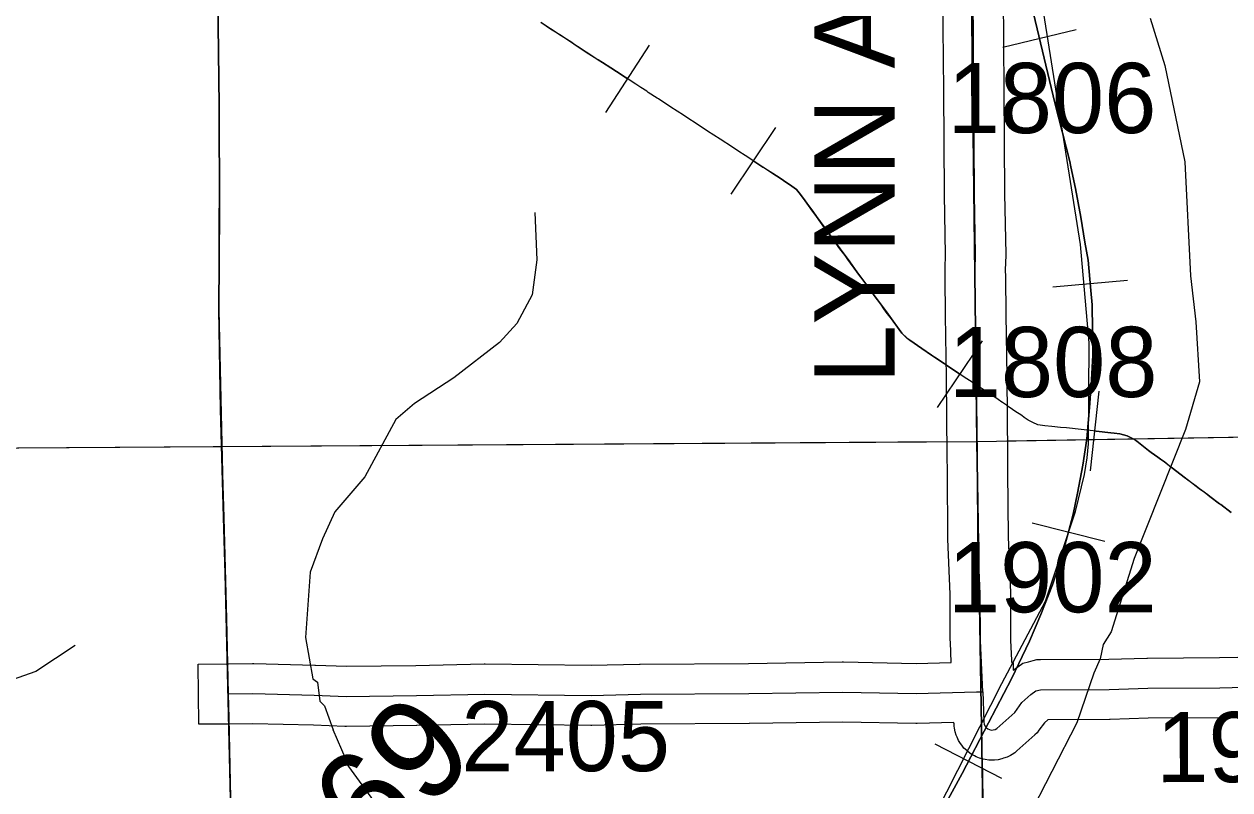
# Model space of a CAD drawing. Extents: x 23.6 to 68.7, y -63 to -29.
# Drawn here: x 43.662 to 44.865, y -42.96 to -42.196 of the extents above; entities that cross this region are included whole.
import ezdxf

# ---------------------------------------------------------------- set-up
doc = ezdxf.new("R2010")
doc.units = 0
for name, color, linetype in [('tdCoHydroRiver', 7, 'Continuous'), ('tdCoPipe', 7, 'Continuous'), ('tdCoPriCL', 7, 'Continuous'), ('tdCoPrimary', 7, 'Continuous'), ('tdCoPriNonDiv', 7, 'Continuous'), ('tdCoPriNonDivCL', 7, 'Continuous'), ('tdCoRRCL', 7, 'Continuous'), ('tdCoSecRdNmbr', 7, 'Continuous'), ('tdCoSecRdTxt', 7, 'Continuous'), ('tdCoSecRteBand', 7, 'Continuous'), ('tdCoSecRteCL', 7, 'Continuous'), ('tdCoSectLine', 7, 'Continuous'), ('tdCoSectLinePart', 7, 'Continuous'), ('tdCoSurfEarth', 7, 'Continuous'), ('tdCoSurfGravel', 7, 'Continuous'), ('tdCoTwpBndry', 7, 'Continuous'), ('tdCoTwpBndryShd', 7, 'Continuous'), ('tdStHwyPriRefPost1', 7, 'Continuous')]:
    doc.layers.add(name, color=color, linetype=linetype)

msp = doc.modelspace()

# ---------------------------------------------------------------- linework, layer by layer
at = {"layer": 'tdCoHydroRiver'}
for points in [[(44.7854, -42.19), (44.8, -42.2372), (44.8199, -42.3333), (44.8257, -42.4469), (44.8309, -42.4927), (44.8346, -42.5526), (44.8208, -42.6001), (44.7696, -42.7289), (44.7465, -42.802), (44.7387, -42.8148), (44.7356, -42.8291), (44.7294, -42.8434), (44.7124, -42.8927)], [(44.1716, -42.3837), (44.1736, -42.431), (44.1692, -42.4658), (44.1537, -42.4944), (44.1365, -42.5135), (44.0911, -42.5486), (44.0519, -42.5743), (44.0331, -42.5902), (44.0021, -42.6473), (43.9724, -42.6824), (43.96, -42.7093), (43.9477, -42.7426), (43.943, -42.8078), (43.9503, -42.849), (43.9551, -42.8522), (43.9572, -42.8712), (43.962, -42.876), (43.9705, -42.8997)], [(43.7132, -42.8158), (43.674, -42.8415), (43.6048, -42.8658), (43.5655, -42.8851), (43.4994, -42.9053)], [(44.7124, -42.8927), (44.6625, -42.9899), (44.6185, -43.0236), (44.6122, -43.0348), (44.6013, -43.0587), (44.6, -43.0967), (44.594, -43.1411), (44.5708, -43.1903), (44.5489, -43.2158), (44.5096, -43.2351), (44.4388, -43.2547), (44.4088, -43.255), (44.3883, -43.2536), (44.3633, -43.2807), (44.2894, -43.3145)], [(44.2894, -43.3145), (44.2875, -43.2798), (44.2746, -43.2562), (44.2587, -43.2375), (44.2457, -43.2044), (44.2408, -43.1887), (44.2264, -43.1683), (44.2007, -43.1432), (44.1271, -43.0979), (44.0548, -43.0304), (43.9837, -42.9328), (43.9836, -42.9297), (43.9705, -42.8997)]]:
    msp.add_lwpolyline(points, dxfattribs=at)
at = {"layer": 'tdCoPipe'}
for p, q in [((44.2424, -42.2839), (44.2862, -42.2168)), ((44.3677, -42.3656), (44.4122, -42.2989)), ((44.5732, -42.5781), (44.6181, -42.5117)), ((44.7258, -42.6415), (44.7346, -42.5619))]:
    msp.add_line(p, q, dxfattribs=at)
for points in [[(44.1777, -42.194), (44.1874, -42.2004), (44.1982, -42.2073), (44.2087, -42.2141), (44.2106, -42.2156), (44.217, -42.2197), (44.223, -42.2237), (44.2337, -42.2306), (44.2349, -42.2314), (44.2392, -42.2341), (44.2475, -42.2394), (44.2587, -42.2467), (44.2601, -42.2477), (44.2617, -42.2487), (44.2643, -42.2503)], [(44.8193, -42.6476), (44.8077, -42.6389), (44.8045, -42.6365), (44.7996, -42.6325), (44.7959, -42.6298), (44.7931, -42.6278), (44.7865, -42.6232), (44.7838, -42.6211), (44.7721, -42.612), (44.7693, -42.6097), (44.7625, -42.6065), (44.7588, -42.6055), (44.7551, -42.6045), (44.7495, -42.6038), (44.7463, -42.6036), (44.7316, -42.6019), (44.7167, -42.6003), (44.7021, -42.5987), (44.6961, -42.5981), (44.6873, -42.5971), (44.6805, -42.5964), (44.6735, -42.5954), (44.6683, -42.5932), (44.6636, -42.5908), (44.6598, -42.5882), (44.6574, -42.5864), (44.6506, -42.5818), (44.6481, -42.5801), (44.6458, -42.5786), (44.6454, -42.5783), (44.6452, -42.5781), (44.6439, -42.5772), (44.6434, -42.5769), (44.6429, -42.5766), (44.6421, -42.576), (44.641, -42.5753), (44.6402, -42.5747), (44.6397, -42.5744), (44.6392, -42.5741), (44.6381, -42.5733), (44.6377, -42.573), (44.6374, -42.5728), (44.6338, -42.5704), (44.6265, -42.5654), (44.623, -42.5631), (44.617, -42.5591), (44.6051, -42.5513), (44.6027, -42.5497), (44.5961, -42.5453), (44.5933, -42.5434), (44.5837, -42.5371), (44.581, -42.5352), (44.58, -42.5345), (44.5702, -42.5279), (44.5672, -42.526), (44.5577, -42.5195), (44.5456, -42.511), (44.543, -42.5093), (44.5377, -42.5041), (44.5352, -42.5006), (44.5274, -42.4899), (44.5223, -42.4831), (44.5192, -42.4787), (44.5174, -42.4762), (44.5135, -42.4709), (44.5103, -42.4666), (44.5071, -42.4623), (44.5018, -42.455), (44.4968, -42.4483), (44.4936, -42.4439), (44.4929, -42.4429), (44.484, -42.4307), (44.4812, -42.4268), (44.4761, -42.42), (44.4679, -42.4087), (44.4669, -42.4074), (44.4608, -42.3991), (44.4526, -42.3879), (44.4488, -42.3825), (44.4447, -42.3769), (44.4413, -42.3721), (44.4366, -42.3657), (44.4327, -42.3609), (44.4258, -42.3558), (44.4231, -42.3541), (44.4163, -42.3496), (44.4091, -42.3449), (44.4038, -42.3414), (44.3992, -42.3384), (44.3912, -42.3332), (44.3891, -42.3318), (44.3816, -42.3269), (44.3753, -42.3228), (44.369, -42.3187), (44.3566, -42.3107), (44.3441, -42.3025), (44.3326, -42.2951), (44.3242, -42.2895), (44.3201, -42.2868), (44.3075, -42.2787), (44.295, -42.2704), (44.2939, -42.2698), (44.2849, -42.2639), (44.2833, -42.2628), (44.2776, -42.2591), (44.2726, -42.2559), (44.2617, -42.2487), (44.2601, -42.2477), (44.2587, -42.2468), (44.2475, -42.2394), (44.2392, -42.2341), (44.2348, -42.2314), (44.2337, -42.2307), (44.223, -42.2237), (44.217, -42.2198), (44.2106, -42.2157), (44.2086, -42.2141), (44.1981, -42.2074), (44.1874, -42.2004), (44.1777, -42.1941)], [(44.3899, -42.3323), (44.3913, -42.3332), (44.3992, -42.3384), (44.4038, -42.3413), (44.4092, -42.3448), (44.4164, -42.3495), (44.4232, -42.354), (44.4258, -42.3557), (44.4328, -42.3609), (44.4367, -42.3657), (44.4413, -42.3721), (44.4448, -42.3769), (44.4489, -42.3824), (44.4526, -42.3878), (44.4609, -42.399), (44.4669, -42.4073), (44.468, -42.4087), (44.4762, -42.42), (44.4813, -42.4268), (44.4841, -42.4307), (44.4929, -42.4428), (44.4936, -42.4439), (44.4969, -42.4483), (44.5019, -42.4549), (44.5072, -42.4623), (44.5103, -42.4665), (44.5135, -42.4709), (44.5175, -42.4762), (44.5192, -42.4786), (44.5224, -42.483), (44.5275, -42.4898), (44.5352, -42.5006), (44.5378, -42.5041), (44.5431, -42.5092), (44.5456, -42.511), (44.5578, -42.5195), (44.5672, -42.526), (44.5702, -42.5279), (44.58, -42.5344), (44.581, -42.5352), (44.5837, -42.5371), (44.5933, -42.5433), (44.5956, -42.5449)], [(44.7302, -42.6017), (44.7316, -42.6019), (44.7463, -42.6035), (44.7495, -42.6038), (44.7551, -42.6045), (44.7588, -42.6054), (44.7625, -42.6064), (44.7694, -42.6097), (44.7722, -42.612), (44.7839, -42.6211), (44.7866, -42.6231), (44.7931, -42.6277), (44.7959, -42.6298), (44.7996, -42.6324), (44.8046, -42.6364), (44.8078, -42.6389), (44.8193, -42.6476), (44.8268, -42.6532), (44.8313, -42.6566), (44.8348, -42.6593), (44.8395, -42.6627), (44.8431, -42.6655), (44.845, -42.6669), (44.8546, -42.6742), (44.8558, -42.675), (44.8663, -42.6831)], [(44.8662, -42.6831), (44.8558, -42.6751), (44.8546, -42.6742), (44.8449, -42.6669), (44.843, -42.6655), (44.8394, -42.6627), (44.8347, -42.6593), (44.8313, -42.6567), (44.8268, -42.6533), (44.8193, -42.6476)]]:
    msp.add_lwpolyline(points, dxfattribs=at)
at = {"layer": 'tdCoPriCL'}
msp.add_lwpolyline([(43.8681, -42.9678), (43.8666, -42.8879), (43.866, -42.864), (43.8641, -42.7892), (43.8614, -42.6879), (43.8599, -42.6378), (43.8582, -42.5801), (43.8565, -42.481), (43.8572, -42.3809), (43.857, -42.2775), (43.8555, -42.1698)], dxfattribs=at)
at = {"layer": 'tdCoPrimary'}
for points in [[(43.8684, -42.9678), (43.867, -42.8879), (43.8664, -42.864), (43.8645, -42.7892), (43.8618, -42.6879), (43.8586, -42.5801), (43.8569, -42.481), (43.8576, -42.3809), (43.8573, -42.2775), (43.8559, -42.1698), (43.8549, -42.12), (43.8549, -42.12), (43.8549, -42.1189), (43.8546, -42.1067), (43.8536, -42.0561), (43.8524, -41.9537), (43.8514, -41.8544), (43.8495, -41.7532), (43.8472, -41.6452), (43.847, -41.6185), (43.847, -41.6174), (43.8463, -41.5389), (43.8448, -41.4292)], [(43.8787, -43.7848), (43.8769, -43.7081), (43.8758, -43.6223), (43.8758, -43.6211), (43.8755, -43.5917), (43.8739, -43.4871), (43.8731, -43.3806), (43.8721, -43.2778), (43.8721, -43.1688), (43.8707, -43.0672), (43.8684, -42.9678), (43.867, -42.8879), (43.8664, -42.864), (43.8645, -42.7892), (43.8618, -42.6879), (43.8586, -42.5801), (43.8569, -42.481), (43.8576, -42.3809), (43.8573, -42.2775), (43.8559, -42.1698), (43.8549, -42.12), (43.8549, -42.12)], [(43.8787, -43.7848), (43.8769, -43.7081), (43.8758, -43.6223), (43.8758, -43.6211), (43.8755, -43.5917), (43.8739, -43.4871), (43.8731, -43.3806), (43.8721, -43.2778), (43.8721, -43.1688), (43.8707, -43.0672), (43.8684, -42.9678), (43.867, -42.8879), (43.8664, -42.864), (43.8645, -42.7892), (43.8618, -42.6879), (43.8586, -42.5801), (43.8569, -42.481), (43.8576, -42.3809), (43.8573, -42.2775), (43.8559, -42.1698), (43.8549, -42.12), (43.8549, -42.12)]]:
    msp.add_lwpolyline(points, dxfattribs=at)
at = {"layer": 'tdCoPriNonDiv'}
msp.add_lwpolyline([(43.842, -41.2171), (43.8469, -41.6452), (43.8511, -41.8543), (43.857, -42.2775), (43.8565, -42.481), (43.8614, -42.6879), (43.8703, -43.0672), (43.8718, -43.2778), (43.8756, -43.6222), (43.8803, -43.9459), (43.8749, -44.0154), (43.8628, -44.0916), (43.8167, -44.3227), (43.8123, -44.358), (43.8117, -44.3699), (43.8118, -44.3937), (43.8137, -44.4174), (43.8153, -44.4292), (43.8226, -44.4642), (43.8502, -44.5643), (43.9089, -44.754), (43.9481, -44.8684), (44.0764, -45.2331), (44.1307, -45.3417)], dxfattribs=at)
at = {"layer": 'tdCoPriNonDivCL'}
msp.add_lwpolyline([(43.8681, -42.9678), (43.8666, -42.8879), (43.866, -42.864), (43.8641, -42.7892), (43.8614, -42.6879), (43.8582, -42.5801), (43.8565, -42.481), (43.8572, -42.3809), (43.857, -42.2775), (43.8555, -42.1698), (43.8545, -42.12), (43.8545, -42.12), (43.8545, -42.1189), (43.8543, -42.1067), (43.8533, -42.0561), (43.852, -41.9537), (43.8511, -41.8544), (43.8491, -41.7532), (43.8469, -41.6452), (43.8466, -41.6185), (43.8466, -41.6174), (43.8459, -41.5389), (43.8448, -41.4595), (43.8444, -41.4292)], dxfattribs=at)
msp.add_lwpolyline([(43.8681, -42.9678), (43.8666, -42.8879), (43.866, -42.864), (43.8641, -42.7892), (43.8614, -42.6879), (43.8582, -42.5801), (43.8565, -42.481), (43.8572, -42.3809), (43.857, -42.2775), (43.8555, -42.1698), (43.8545, -42.12), (43.8545, -42.12), (43.8545, -42.1189), (43.8543, -42.1067), (43.8533, -42.0561), (43.852, -41.9537), (43.8511, -41.8544), (43.8491, -41.7532), (43.8469, -41.6452), (43.8466, -41.6185), (43.8466, -41.6174), (43.8459, -41.5389), (43.8448, -41.4595), (43.8444, -41.4292)], dxfattribs=at)
at = {"layer": 'tdCoRRCL'}
for p, q in [((44.7115, -42.2017), (44.6385, -42.219)), ((44.7629, -42.4516), (44.6882, -42.4581)), ((44.7403, -42.7119), (44.6676, -42.6935)), ((44.6375, -42.9485), (44.5709, -42.914))]:
    msp.add_line(p, q, dxfattribs=at)
for points in [[(44.3629, -43.3944), (44.6376, -42.8537), (44.6811, -42.7713), (44.7109, -42.682), (44.7201, -42.6452), (44.7225, -42.6285), (44.7239, -42.6146), (44.7246, -42.5136), (44.7158, -42.4158), (44.6459, -41.9735)], [(44.669, -42.1851), (44.6902, -42.2745), (44.7052, -42.333), (44.7063, -42.3382), (44.7109, -42.3597), (44.7162, -42.3883), (44.7204, -42.4132), (44.7235, -42.4313), (44.7261, -42.4614), (44.7275, -42.4759), (44.728, -42.5008), (44.7282, -42.5262), (44.7269, -42.5506), (44.7248, -42.5784), (44.7222, -42.6096), (44.7183, -42.6358), (44.713, -42.6636), (44.7086, -42.6845), (44.7028, -42.7073), (44.696, -42.7315), (44.6879, -42.7553), (44.6763, -42.7847), (44.6651, -42.8114), (44.647, -42.8489), (44.6242, -42.8927), (44.598, -42.9433), (44.5717, -42.9915)], [(44.5717, -42.9915), (44.598, -42.9433), (44.6242, -42.8927), (44.647, -42.8489), (44.6651, -42.8114), (44.6763, -42.7847), (44.6879, -42.7553), (44.696, -42.7315), (44.7028, -42.7073), (44.7086, -42.6845), (44.713, -42.6636), (44.7183, -42.6358), (44.7222, -42.6096), (44.7248, -42.5784), (44.7269, -42.5506), (44.7282, -42.5262), (44.728, -42.5008), (44.7275, -42.4759), (44.7261, -42.4614), (44.7235, -42.4313), (44.7204, -42.4132), (44.7162, -42.3883), (44.7109, -42.3597), (44.7063, -42.3382), (44.7052, -42.333), (44.6902, -42.2745), (44.669, -42.1851)]]:
    msp.add_lwpolyline(points, dxfattribs=at)
at = {"layer": 'tdCoSecRteBand'}
for points in [[(44.8924, -42.887), (44.8557, -42.8878), (44.8554, -42.8878), (44.8552, -42.8878), (44.7835, -42.8883), (44.7456, -42.8894), (44.7452, -42.8894), (44.7448, -42.8894), (44.6834, -42.8897), (44.6799, -42.8929), (44.6745, -42.9002), (44.6727, -42.9027), (44.6704, -42.9048), (44.6526, -42.9207), (44.6504, -42.9227), (44.6477, -42.9243), (44.6461, -42.9253), (44.6429, -42.9271), (44.6393, -42.9282), (44.6374, -42.9287), (44.6339, -42.9298), (44.6302, -42.9299), (44.6282, -42.93), (44.6245, -42.9301), (44.6209, -42.9294), (44.6189, -42.929), (44.6153, -42.9282), (44.612, -42.9266), (44.6102, -42.9257), (44.6069, -42.9241), (44.604, -42.9217), (44.6025, -42.9204), (44.5997, -42.9181), (44.5975, -42.9151), (44.5964, -42.9135), (44.5942, -42.9105), (44.5928, -42.907), (44.5921, -42.9052), (44.5908, -42.9018), (44.5903, -42.8981), (44.59, -42.8961), (44.5898, -42.8948), (44.5898, -42.8935), (44.5897, -42.8932), (44.5897, -42.8932), (44.5897, -42.8925), (44.5531, -42.8936), (44.5523, -42.8936), (44.5516, -42.8936), (44.4788, -42.8921), (44.3858, -42.8936), (44.3857, -42.8936), (44.3855, -42.8936), (44.2774, -42.8942), (44.2287, -42.8954), (44.2282, -42.8954), (44.2276, -42.8954), (44.1219, -42.8941), (44.0542, -42.8956), (44.0541, -42.8956), (44.0539, -42.8956), (43.984, -42.8964), (43.9832, -42.8964), (43.9824, -42.8964), (43.9509, -42.8952), (43.8904, -42.8937), (43.8667, -42.894), (43.8367, -42.8943), (43.8361, -42.8343), (43.8661, -42.834), (43.8903, -42.8337), (43.8908, -42.8337), (43.8914, -42.8337), (43.9525, -42.8352), (43.9527, -42.8352), (43.953, -42.8352), (43.984, -42.8364), (44.053, -42.8356), (44.1211, -42.8341), (44.1216, -42.8341), (44.1222, -42.8341), (44.2278, -42.8354), (44.2763, -42.8343), (44.2765, -42.8342), (44.2768, -42.8342), (44.385, -42.8336), (44.4784, -42.8321), (44.4789, -42.8321), (44.4795, -42.8321), (44.552, -42.8336), (44.5871, -42.8325), (44.5862, -42.8123), (44.5862, -42.8117), (44.5861, -42.8111), (44.586, -42.7646), (44.5837, -42.7095), (44.5837, -42.709), (44.5837, -42.7085), (44.5832, -42.6427), (44.5831, -42.6263), (44.5824, -42.5485), (44.5814, -42.4864), (44.5814, -42.4864), (44.5814, -42.4863), (44.581, -42.4485), (44.5809, -42.4409), (44.5809, -42.4402), (44.5809, -42.4396), (44.5814, -42.4256), (44.5803, -42.366), (44.5803, -42.3658), (44.5803, -42.3656), (44.5796, -42.2621), (44.5788, -42.1679)], [(44.6388, -42.1671), (44.6396, -42.2616), (44.6396, -42.2617), (44.6396, -42.2617), (44.6403, -42.3651), (44.6414, -42.4252), (44.6414, -42.426), (44.6414, -42.4268), (44.6409, -42.4409), (44.641, -42.4478), (44.6414, -42.4856), (44.6424, -42.5476), (44.6424, -42.5477), (44.6424, -42.5479), (44.643, -42.6258), (44.643, -42.6258), (44.643, -42.6258), (44.6432, -42.6422), (44.6437, -42.7075), (44.646, -42.7627), (44.646, -42.7633), (44.646, -42.7639), (44.6461, -42.8103), (44.647, -42.8306), (44.6471, -42.8324), (44.6489, -42.8325), (44.6488, -42.8404)], [(44.6488, -42.8404), (44.6536, -42.8368), (44.6584, -42.8333), (44.6642, -42.8318), (44.6688, -42.8307), (44.6724, -42.8298), (44.676, -42.8298), (44.7442, -42.8294), (44.7821, -42.8283), (44.7824, -42.8283), (44.7828, -42.8283), (44.8546, -42.8278), (44.8913, -42.827)]]:
    msp.add_lwpolyline(points, dxfattribs=at)
at = {"layer": 'tdCoSecRteCL'}
for points in [[(44.6184, -42.8619), (44.6161, -42.811), (44.616, -42.764), (44.6137, -42.7082), (44.6132, -42.6424), (44.6131, -42.626), (44.6124, -42.5481), (44.6114, -42.486), (44.611, -42.4482), (44.6109, -42.4406), (44.6114, -42.4258), (44.6103, -42.3655), (44.6096, -42.2619), (44.6088, -42.1673)], [(44.6184, -42.8619), (44.6188, -42.871), (44.6197, -42.8921), (44.62, -42.8941), (44.6207, -42.8959), (44.6219, -42.8975), (44.6234, -42.8988), (44.6251, -42.8996), (44.627, -42.9), (44.629, -42.8999), (44.6309, -42.8994), (44.6326, -42.8984), (44.6503, -42.8824), (44.6575, -42.8726), (44.6664, -42.8647), (44.6715, -42.8609), (44.6761, -42.8598), (44.7447, -42.8594), (44.783, -42.8583), (44.855, -42.8578), (44.892, -42.857)], [(43.8664, -42.864), (43.8906, -42.8637), (43.9518, -42.8652), (43.9836, -42.8664), (44.0536, -42.8656), (44.1218, -42.8641), (44.228, -42.8654), (44.277, -42.8642), (44.3853, -42.8636), (44.4789, -42.8621), (44.5522, -42.8636), (44.6124, -42.8618), (44.6184, -42.8619)]]:
    msp.add_lwpolyline(points, dxfattribs=at)
at = {"layer": 'tdCoSectLine'}
for points in [[(44.6006, -41.6086), (44.6126, -42.6121)], [(44.6126, -42.6121), (45.5964, -42.5957)], [(43.6067, -42.6188), (44.6126, -42.6121)], [(44.6126, -42.6121), (44.6289, -43.6086)]]:
    msp.add_lwpolyline(points, dxfattribs=at)
at = {"layer": 'tdCoSectLinePart'}
for points in [[(44.6425, -42.6116), (45.5667, -42.5962)], [(43.6067, -42.6188), (44.5825, -42.6123)], [(44.6178, -42.9282), (44.6284, -43.5791)]]:
    msp.add_lwpolyline(points, dxfattribs=at)
at = {"layer": 'tdCoSurfEarth'}
for points in [[(44.6184, -42.8619), (44.6161, -42.811), (44.616, -42.764), (44.6137, -42.7082), (44.6132, -42.6424), (44.6131, -42.626), (44.6124, -42.5481), (44.6114, -42.486), (44.611, -42.4482)], [(44.6184, -42.8619), (44.6188, -42.871), (44.6197, -42.8921), (44.62, -42.8941), (44.6207, -42.8959), (44.6219, -42.8975), (44.6234, -42.8988), (44.6251, -42.8996), (44.627, -42.9), (44.629, -42.8999), (44.6309, -42.8994), (44.6326, -42.8984), (44.6503, -42.8824), (44.6575, -42.8726), (44.6664, -42.8647), (44.6715, -42.8609), (44.6761, -42.8598), (44.7447, -42.8594), (44.783, -42.8583), (44.855, -42.8578), (44.892, -42.857)], [(43.8664, -42.864), (43.8906, -42.8637), (43.9518, -42.8652), (43.9836, -42.8664), (44.0536, -42.8656), (44.1218, -42.8641), (44.228, -42.8654), (44.277, -42.8642), (44.3853, -42.8636), (44.4789, -42.8621), (44.5522, -42.8636), (44.6124, -42.8618), (44.6184, -42.8619)]]:
    msp.add_lwpolyline(points, dxfattribs=at)
at = {"layer": 'tdCoSurfGravel'}
msp.add_lwpolyline([(44.611, -42.4482), (44.6109, -42.4406), (44.6114, -42.4258), (44.6103, -42.3655), (44.6096, -42.2619), (44.6088, -42.1673), (44.6066, -42.0991), (44.6042, -42.0575), (44.6035, -42.0254)], dxfattribs=at)
at = {"layer": 'tdCoTwpBndry'}
msp.add_lwpolyline([(44.6284, -43.5783), (44.6178, -42.9287)], dxfattribs=at)
at = {"layer": 'tdCoTwpBndryShd'}
msp.add_lwpolyline([(45.4662, -47.5782), (45.2886, -47.5798), (45.2913, -47.032), (44.6825, -47.037), (44.6731, -46.5813), (44.659, -45.6063), (44.6438, -44.6042), (44.6289, -43.6086), (44.6126, -42.6121), (44.6006, -41.6086), (44.596, -40.6132), (44.5679, -39.6075), (44.5586, -38.6082), (44.5434, -37.6076), (44.5249, -36.6101), (44.5204, -35.6065), (44.4936, -34.6124), (44.4817, -33.64)], dxfattribs=at)

# ---------------------------------------------------------------- texts
at = {"layer": 'tdCoSecRdNmbr'}
for s, rotation, p in [('1806', 0.0348, (44.5834, -42.3046)), ('1808', 0.0348, (44.5845, -42.5679)), ('1902', 0.0348, (44.5837, -42.7826)), ('2405', 0.0344, (44.0984, -42.9411)), ('1903', 0.0349, (44.7915, -42.952))]:
    msp.add_text(s, height=0.07, rotation=rotation, dxfattribs=at).set_placement(p)
at = {"layer": 'tdCoSecRdTxt'}
msp.add_text('LYNN AVE', height=0.08, rotation=90, dxfattribs=at).set_placement((44.5305, -42.5551))
at = {"layer": 'tdStHwyPriRefPost1'}
msp.add_text('‒‒69', height=0.1, rotation=45, dxfattribs=at).set_placement((43.9062, -43.1378))

doc.saveas('drawing.dxf')
